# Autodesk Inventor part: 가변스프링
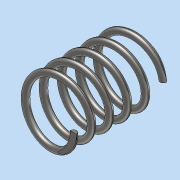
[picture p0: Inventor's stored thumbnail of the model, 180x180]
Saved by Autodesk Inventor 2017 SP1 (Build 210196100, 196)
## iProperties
Part Number: 가변스프링
Material: 스테인레스 스틸
Document SubType Name: Modeling
Designer: MRC
Density: 8 g/cm^3
Appearance: 반연마
Mass: 6.99869 g
Surface Area: 17.7562 cm^2
Volume: 0.874837 cm^3
Author: MRC
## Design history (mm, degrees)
sketch "스케치1"
  geometry: L1 (0, 0)-(9, 0); L2 (9, 0)-(9, -28.5); L3 (9, -28.5)-(0, -28.5); L4 (0, -28.5)-(0, 0); C1 r 1 at (9, 0)
  constraints: 8 end point, 2 parallel, 1 centre point, 1 coincident, 1 horizontal, 1 perpendicular
  dimensions: "d0" = 18 diameter of L2 L4; "d1" = 2 diameter of C1; "d2" = 28.5 distance between parallel lines of L1 L3 (derived)
feature "코일1" sketch "스케치1" pitch "d3" = 10; turns "d5" = 5; dims "d4" = 28.5 (= d2), "d6" = 0, angle "d7" = 90 deg, angle "d8" = 90 deg, "d9" = 0, "d10" = 0
sketch "스케치2"
  geometry: L1 (-20.357, -28.5)-(20.357, -28.5); L2 (20.357, -28.5)-(20.357, 0); L3 (20.357, 0)-(-20.357, 0); L4 (-20.357, 0)-(-20.357, -28.5); L5 (9, -28.5)-(0, -28.5) reference; 2 further points
  constraints: 8 end point, 2 midpoint, 2 parallel, 1 coincident, 1 horizontal, 1 perpendicular
  dimensions: "d11" = 40.71422 distance of L1.start L1.end
extrude "돌출1" sketch "스케치2" stored distance "d12" = 0; taper "d13" = 0 deg
node "솔리드1"
